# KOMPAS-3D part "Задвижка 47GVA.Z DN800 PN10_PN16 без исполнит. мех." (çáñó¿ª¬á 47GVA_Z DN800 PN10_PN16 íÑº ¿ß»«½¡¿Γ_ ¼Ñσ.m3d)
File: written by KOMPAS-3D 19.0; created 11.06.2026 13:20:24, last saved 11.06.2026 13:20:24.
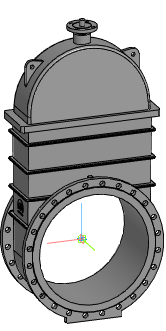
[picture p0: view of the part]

Document properties: Автор: Евгений; Полное имя файла: Z:\3.Личные\kachalov\001_3d для проектировщиков\2.2 Тип 47GVA, 47GVA.Z\_stp\_stp_Задвижка 47GVA.Z DN350-DN1200 без исп.мех\Задвижка 47GVA_Z DN800 PN10_PN16 без исполнит_ мех.m3d

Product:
- Part/product: Задвижка 47GVA.Z DN800 PN10_PN16 без исполнит. мех.

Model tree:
1. Операция без истории:1  (labels: Задвижка 47GVA.Z DN800 PN10_PN16 без исполнит. мех.)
